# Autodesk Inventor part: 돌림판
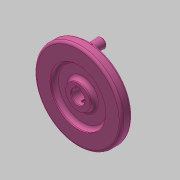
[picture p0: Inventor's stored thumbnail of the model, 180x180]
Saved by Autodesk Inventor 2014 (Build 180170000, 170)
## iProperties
Created: 2019-09
Part Number: 돌림판
Material: 알루미늄 6061
Document SubType Name: Modeling
Designer: mduedu
Density: 2.71 g/cm^3
Mass: 83.7217 g
Surface Area: 107.333 cm^2
Volume: 30.8936 cm^3
Appearance: 분홍색
Author: mduedu
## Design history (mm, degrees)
sketch "스케치1"
  geometry: L1 (0, 0)-(9, 0); L2 (9, 0)-(9, 36); L3 (9, 36)-(0, 36); L4 (0, 23)-(4, 23); L5 (4, 23)-(4, 10); L6 (4, 10)-(0, 10); L7 (0, 36)-(0, 23); L8 (0, 10)-(0, 0)
  constraints: 16 end point, 4 parallel, 2 horizontal, 2 perpendicular, 1 collinear
  dimensions: "d0" = 72 diameter of L3 L1; "d2" = 9 distance of L2.end L3.end; "d3" = 4 distance between parallel lines of L7 L5; "d4" = 20 diameter of L6 L1; "d5" = 46 diameter of L4 L1
revolve "회전1" sketch "스케치1" stored, may be unused: angle "d6" = 90 deg
fillet "모깎기1" dims "d7" = 3
sketch "스케치2"
  geometry: C1 r 4 at (0, 29); 1 further point
  constraints: 1 centre point, 1 vertical alignment
  dimensions: "d8" = 8 diameter of C1; "d9" = 29 distance of C1.centre point (0, 0)
extrude "돌출1" join sketch "스케치2" distance "d10" = 11; taper "d11" = 0 deg
fillet "모깎기2" dims "d12" = 2
fillet "모깎기3" dims "d13" = 2
chamfer "모따기1" distance "d14" = 1; stored, may be unused: second distance "d15" = 2, angle "d16" = 45 deg
sketch "스케치3"
  geometry: L1 (-2, 5.123)-(2, 5.123); L2 (2, 5.123)-(2, 7.3); L3 (2, 7.3)-(-2, 7.3); L4 (-2, 7.3)-(-2, 5.123); A1 r 5.5 centre (0, 0) between (-2, 5.123) and (2, 5.123); 1 further point
  constraints: 8 end point, 2 parallel, 2 point on circle, 1 centre point, 1 coincident, 1 horizontal, 1 perpendicular
  dimensions: "d17" = 11 diameter of A1; "d18" = 4 distance of L2.end L3.end; "d19" = 12.8 dimension on A1 L3
extrude "돌출2" cut sketch "스케치3" stored distance "d20" = 11; taper "d21" = 0 deg
chamfer "모따기2" distance "d22" = 0.5; stored, may be unused: second distance "d23" = 2, angle "d24" = 45 deg
sketch "스케치4"
  geometry: A1 r 5.5 centre (0, 0) between (-2, 5.123) and (2, 5.123) reference; 2 further points
  constraints: 1 point on circle
hole "구멍1" sketch "스케치4" at (0, -5.5) diameter "d25" = 2.459; stored, may be unused: countersink angle "d29" = 90 deg, drill point angle "d31" = 118 deg; dims "d26" = 6, "d27" = 4, "d28" = 2, "d30" = 5
node "솔리드1"
